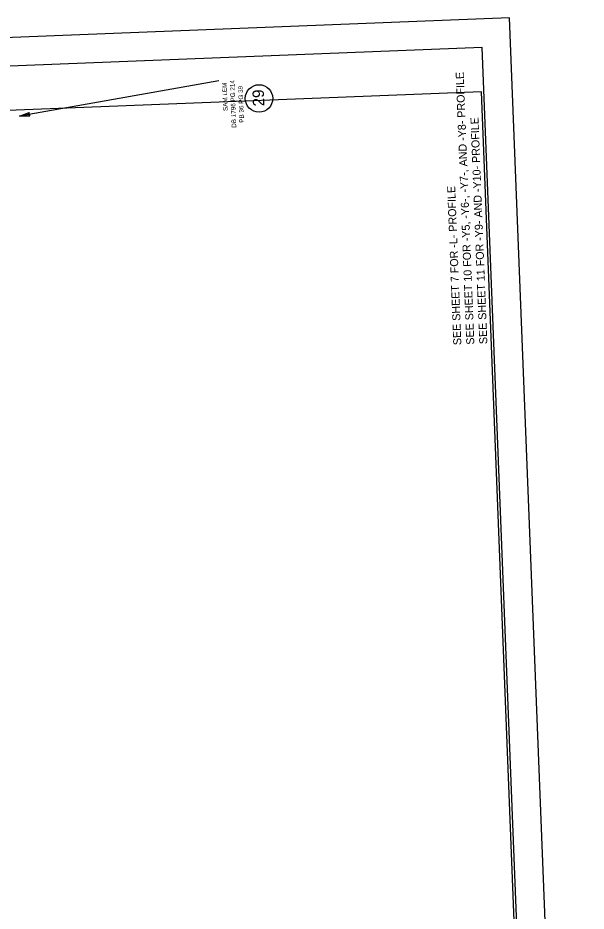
# Model space of a CAD drawing. Extents: x 1627855 to 1629021, y 762567 to 764488.
# Drawn here: x 1628524 to 1629021, y 763528 to 764309 of the extents above; entities that cross this region are included whole.
import ezdxf

# ---------------------------------------------------------------- set-up
doc = ezdxf.new("R2010")
doc.units = 0
for name, color, linetype in [('Prop Dimension', 7, 'Continuous'), ('Prop DSN Text', 7, 'Continuous'), ('Prop Parcel Number CELL', 7, 'Continuous'), ('Prop Parcel Owner Text', 7, 'Continuous'), ('Prop Terminator CELL', 7, 'Continuous'), ('Sheet Clip Boundary CELL', 7, 'Continuous'), ('Sheet Plan And Profile CELL', 7, 'Continuous'), ('Sheet Plot Border Outside CELL', 7, 'Continuous')]:
    doc.layers.add(name, color=color, linetype=linetype)

msp = doc.modelspace()

# ---------------------------------------------------------------- linework, layer by layer
at = {"layer": 'Prop Dimension'}
msp.add_line((1628699.87, 764254.41), (1628525.25, 764223.47), dxfattribs=at)
at = {"layer": 'Prop Parcel Number CELL'}
msp.add_line((1628734.93, 764238.9), (1628734.93, 764238.9), dxfattribs=at)
msp.add_circle((1628734.93, 764238.9), 12, dxfattribs=at)
at = {"layer": 'Prop Terminator CELL'}
msp.add_lwpolyline([(1628534.38, 764223.52), (1628525.25, 764223.47), (1628533.88, 764226.63), (1628533.03, 764224.85)], close=True, dxfattribs=at)
at = {"layer": 'Sheet Clip Boundary CELL'}
msp.add_lwpolyline([(1628522.47, 764228.52), (1628282.65, 764219.07), (1628066.45, 764210.34), (1628072.87, 764047.54), (1627958.4, 764043.02), (1627966.27, 763843.29), (1627900.75, 763840.71), (1627941.6, 762804.67), (1628337.82, 762820.15), (1628577.63, 762829.61), (1628634.82, 762831.83), (1628637.13, 762773.12), (1628655.42, 762773.84), (1628653.1, 762832.57), (1628984.86, 762845.59), (1628929.69, 764244.53)], close=True, dxfattribs=at)
at = {"layer": 'Sheet Plan And Profile CELL'}
msp.add_lwpolyline([(1627881.09, 764242.05), (1627940.19, 762743.21), (1628989.38, 762784.59), (1628930.27, 764283.42)], close=True, dxfattribs=at)
at = {"layer": 'Sheet Plot Border Outside CELL'}
msp.add_lwpolyline([(1629021.25, 762610.71), (1628954.27, 764309.39), (1627855.12, 764266.04), (1627922.11, 762567.36)], close=True, dxfattribs=at)

# ---------------------------------------------------------------- texts
at = {"layer": 'Prop DSN Text'}
for s, p in [('SEE SHEET 10 FOR -Y5, -Y6-, -Y7-, AND -Y8- PROFILE', (1628923.43, 764023.63)), ('SEE SHEET 11 FOR -Y9- AND -Y10- PROFILE', (1628934.79, 764024.08)), ('SEE SHEET 7 FOR -L- PROFILE', (1628912.06, 764023.18))]:
    msp.add_text(s, height=7, rotation=92.25819, dxfattribs=at).set_placement(p)
at = {"layer": 'Prop Parcel Number CELL'}
msp.add_text('29', height=10, rotation=92.25819, dxfattribs=at).set_placement((1628739.68, 764232.09))
at = {"layer": 'Prop Parcel Owner Text'}
for s, p in [('DB 1796 PG 214', (1628715.05, 764213.28)), ('SAM LEM', (1628707.55, 764227.97)), ('PB 36 PG 39', (1628721.88, 764217.74))]:
    msp.add_text(s, height=4, rotation=92.25819, dxfattribs=at).set_placement(p)

doc.saveas('drawing.dxf')
